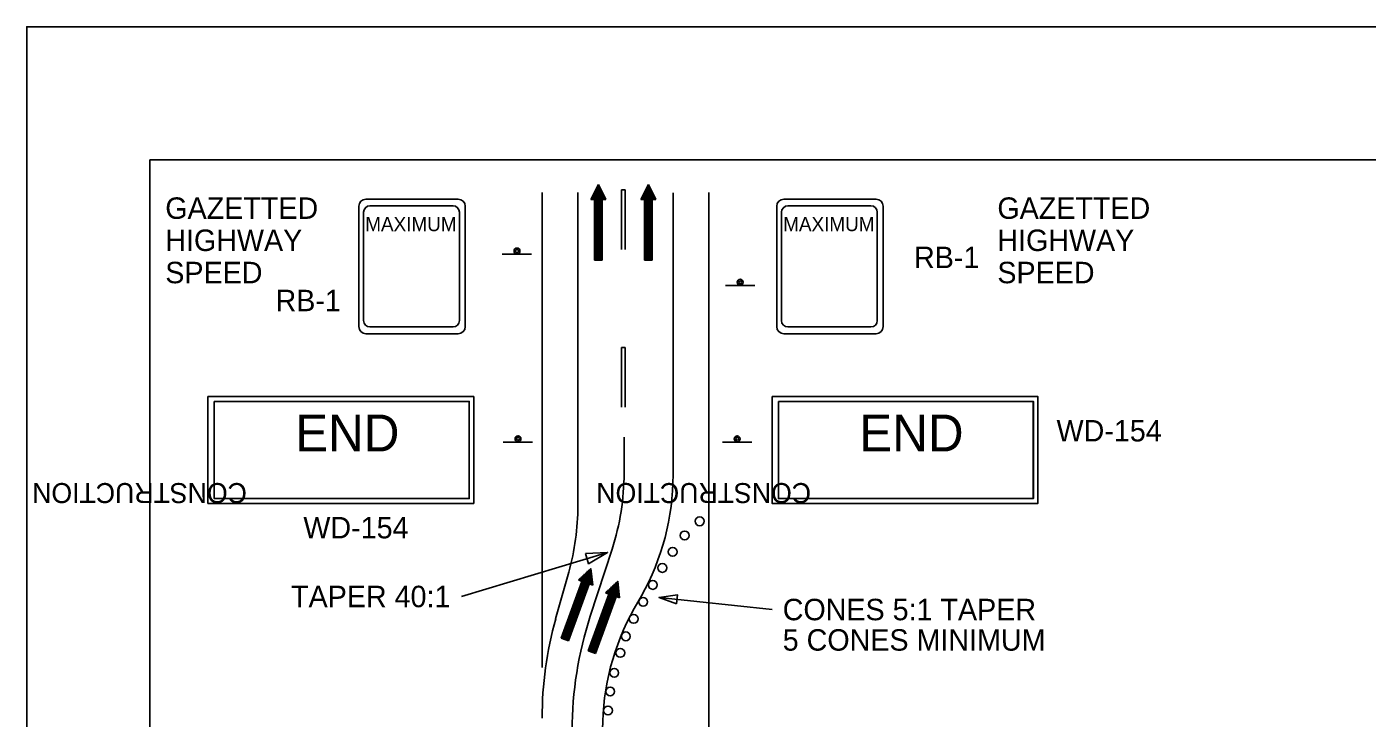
# Model space of a CAD drawing. Extents: x 2171 to 2395, y 134 to 413.
# Drawn here: x 2178.7 to 2287.7, y 356.6 to 412.8 of the extents above; entities that cross this region are included whole.
import ezdxf

# ---------------------------------------------------------------- set-up
doc = ezdxf.new("R2010")
doc.units = 0
for name, color, linetype in [('Level 10', 7, 'Continuous'), ('Level 12', 7, 'Continuous'), ('Level 2', 7, 'Continuous'), ('Level 20', 7, 'Continuous'), ('Level 44', 7, 'Continuous'), ('Level 60', 7, 'Continuous')]:
    doc.layers.add(name, color=color, linetype=linetype)

# ---------------------------------------------------------------- blocks, each defined once
blk = doc.blocks.new('END')
at = {"layer": 'Level 2'}
for points in [[(0, 8.676), (21.598, 8.676), (21.598, 0), (0, 0)], [(0.511, 8.287), (21.224, 8.287), (21.224, 0.397), (0.511, 0.397)]]:
    blk.add_lwpolyline(points, close=True, dxfattribs=at)
at = {"layer": 'Level 44'}
for s, height, rotation, p in [('END', 3, 359.99999, (7.085, 4.219)), ('CONSTRUCTION', 1.62, 179.99999, (3.164, 1.653))]:
    blk.add_text(s, height=height, rotation=rotation, dxfattribs=at).set_placement(p)

msp = doc.modelspace()

# ---------------------------------------------------------------- linework, layer by layer
at = {"layer": 'Level 10'}
for p, q in [((2225.19, 399.95), (2224.58, 398.72)), ((2225.11, 399.8), (2225.11, 393.81)), ((2225.19, 399.95), (2225.19, 393.81)), ((2225.19, 399.95), (2225.8, 398.72)), ((2225.27, 399.8), (2225.27, 393.81)), ((2229.26, 399.95), (2228.64, 398.72)), ((2229.18, 399.8), (2229.18, 393.81)), ((2229.26, 399.95), (2229.26, 393.81)), ((2229.26, 399.95), (2229.87, 398.72)), ((2229.33, 399.8), (2229.33, 393.81)), ((2223.52, 373.85), (2223.52, 399.31)), ((2224.58, 398.72), (2224.88, 398.72)), ((2224.65, 398.88), (2224.65, 398.72)), ((2224.73, 399.03), (2224.73, 398.72)), ((2224.81, 399.18), (2224.81, 398.72)), ((2224.88, 399.34), (2224.88, 393.81)), ((2224.88, 398.72), (2224.88, 393.81)), ((2224.96, 399.49), (2224.96, 393.81)), ((2225.03, 399.64), (2225.03, 393.81)), ((2225.34, 399.64), (2225.34, 393.81)), ((2225.42, 399.49), (2225.42, 393.81)), ((2225.5, 399.34), (2225.5, 393.81)), ((2225.5, 398.72), (2225.5, 393.81)), ((2225.5, 398.72), (2225.8, 398.72)), ((2225.57, 399.18), (2225.57, 398.72)), ((2225.65, 399.03), (2225.65, 398.72)), ((2225.73, 398.88), (2225.73, 398.72)), ((2228.64, 398.72), (2228.95, 398.72)), ((2228.72, 398.88), (2228.72, 398.72)), ((2228.8, 399.03), (2228.8, 398.72)), ((2228.87, 399.18), (2228.87, 398.72)), ((2228.95, 399.34), (2228.95, 393.81)), ((2228.95, 398.72), (2228.95, 393.81)), ((2229.03, 399.49), (2229.03, 393.81)), ((2229.1, 399.64), (2229.1, 393.81)), ((2229.41, 399.64), (2229.41, 393.81)), ((2229.49, 399.49), (2229.49, 393.81)), ((2229.56, 399.34), (2229.56, 393.81)), ((2229.56, 398.72), (2229.56, 393.81)), ((2229.56, 398.72), (2229.87, 398.72)), ((2229.64, 399.18), (2229.64, 398.72)), ((2229.72, 399.03), (2229.72, 398.72)), ((2229.79, 398.88), (2229.79, 398.72)), ((2231.26, 376.36), (2231.26, 399.28)), ((2224.88, 393.81), (2225.5, 393.81)), ((2228.95, 393.81), (2229.56, 393.81)), ((2227.28, 379.44), (2227.28, 376.51)), ((2224.53, 364.88), (2226.3, 370.33)), ((2225.94, 370.07), (2214.07, 366.49)), ((2221.72, 364.68), (2222.78, 368.47)), ((2224.07, 368.3), (2222.18, 363.11)), ((2224.2, 368.42), (2222.26, 363.08)), ((2224.32, 368.54), (2222.33, 363.06)), ((2224.45, 368.65), (2222.4, 363.03)), ((2224.57, 368.77), (2222.47, 363)), ((2224.59, 368.6), (2222.54, 362.98)), ((2224.61, 368.43), (2222.62, 362.95)), ((2224.63, 368.26), (2222.69, 362.93)), ((2224.57, 368.77), (2223.57, 367.83)), ((2223.95, 368.18), (2223.79, 367.75)), ((2224.57, 368.77), (2224.73, 367.41)), ((2223.86, 367.72), (2222.18, 363.11)), ((2224.65, 368.09), (2222.76, 362.9)), ((2224.44, 367.51), (2222.76, 362.9)), ((2223.57, 367.83), (2223.86, 367.72)), ((2223.7, 367.94), (2223.65, 367.8)), ((2223.82, 368.06), (2223.72, 367.78)), ((2226.26, 367.27), (2224.37, 362.08)), ((2224.44, 367.51), (2224.73, 367.41)), ((2226.39, 367.38), (2224.44, 362.05)), ((2224.67, 367.92), (2224.51, 367.49)), ((2226.51, 367.5), (2224.51, 362.03)), ((2224.69, 367.75), (2224.58, 367.46)), ((2226.63, 367.62), (2224.59, 362)), ((2226.76, 367.74), (2224.66, 361.97)), ((2224.71, 367.58), (2224.66, 367.43)), ((2226.78, 367.57), (2224.73, 361.95)), ((2226.8, 367.4), (2224.8, 361.92)), ((2226.82, 367.23), (2224.88, 361.89)), ((2226.84, 367.06), (2224.95, 361.87)), ((2226.76, 367.74), (2225.76, 366.79)), ((2226.14, 367.15), (2225.98, 366.72)), ((2226.76, 367.74), (2226.91, 366.38)), ((2226.05, 366.69), (2224.37, 362.08)), ((2226.63, 366.48), (2224.95, 361.87)), ((2225.76, 366.79), (2226.05, 366.69)), ((2225.89, 366.91), (2225.83, 366.77)), ((2226.01, 367.03), (2225.91, 366.74)), ((2226.63, 366.48), (2226.91, 366.38)), ((2226.86, 366.89), (2226.7, 366.45)), ((2226.88, 366.72), (2226.77, 366.43)), ((2226.9, 366.55), (2226.84, 366.4)), ((2228.11, 365.51), (2228.69, 366.54)), ((2230.13, 366.42), (2239.3, 365.43)), ((2222.18, 363.11), (2222.76, 362.9)), ((2224.37, 362.08), (2224.95, 361.87))]:
    msp.add_line(p, q, dxfattribs=at)
for points in [[(2224.15, 369.98), (2225.94, 370.07), (2224.4, 369.15)], [(2231.54, 365.9), (2230.13, 366.42), (2231.61, 366.63)]]:
    msp.add_lwpolyline(points, close=True, dxfattribs=at)
for centre in [(2233.42, 372.6), (2232.2, 371.45), (2231.23, 370.12), (2230.39, 368.81), (2230.39, 368.81), (2230.39, 368.81), (2229.61, 367.43), (2229.61, 367.43), (2229.61, 367.43), (2228.83, 366.05), (2228.83, 366.05), (2228.83, 366.05), (2228.06, 364.67), (2228.06, 364.67), (2228.06, 364.67), (2227.42, 363.25), (2226.97, 361.91), (2226.48, 360.29), (2226.15, 358.78), (2225.97, 357.23)]:
    msp.add_circle(centre, 0.359, dxfattribs=at)
msp.add_arc((2207.28, 376.51), 20, 341.9995, 0, dxfattribs=at)
at = {"layer": 'Level 12'}
for centre, radius, start, end in [((2211.26, 376.36), 20, 330.6066, 0), ((2203.52, 373.85), 20, 344.3937, 0), ((2253.06, 355.61), 30, 161.9995, 180), ((2245.53, 355.69), 20, 150.6066, 179.9638), ((2250.62, 356.61), 30, 164.3937, 180)]:
    msp.add_arc(centre, radius, start, end, dxfattribs=at)
at = {"layer": 'Level 2'}
for p, q in [((2227.07, 399.51), (2227.07, 394.67)), ((2227.36, 399.51), (2227.07, 399.51)), ((2227.36, 394.67), (2227.36, 399.51)), ((2227.07, 386.7), (2227.07, 381.86)), ((2227.36, 386.7), (2227.07, 386.7)), ((2227.36, 381.86), (2227.36, 386.7))]:
    msp.add_line(p, q, dxfattribs=at)
for points in [[(2193.47, 382.73), (2215.07, 382.73), (2215.07, 374.05), (2193.47, 374.05)], [(2193.98, 382.34), (2214.7, 382.34), (2214.7, 374.44), (2193.98, 374.44)], [(2239.31, 382.73), (2260.91, 382.73), (2260.91, 374.05), (2239.31, 374.05)], [(2239.82, 382.34), (2260.53, 382.34), (2260.53, 374.44), (2239.82, 374.44)]]:
    msp.add_lwpolyline(points, close=True, dxfattribs=at)
at = {"layer": 'Level 20'}
for p, q in [((2220.62, 360.72), (2220.62, 399.31)), ((2234.16, 349.42), (2234.16, 399.31))]:
    msp.add_line(p, q, dxfattribs=at)
at = {"layer": 'Level 44'}
for p, q in [((2206.3, 398.76), (2213.8, 398.76)), ((2240.26, 398.76), (2247.75, 398.76)), ((2205.72, 388.41), (2205.72, 398.18)), ((2206.11, 388.91), (2206.11, 397.7)), ((2206.63, 398.22), (2213.38, 398.22)), ((2213.9, 397.7), (2213.9, 388.91)), ((2214.38, 398.18), (2214.38, 388.41)), ((2239.68, 388.41), (2239.68, 398.18)), ((2240.07, 388.91), (2240.07, 397.7)), ((2240.59, 398.22), (2247.33, 398.22)), ((2247.85, 397.7), (2247.85, 388.91)), ((2248.33, 398.18), (2248.33, 388.41)), ((2217.37, 394.28), (2219.77, 394.28)), ((2235.51, 391.74), (2237.91, 391.74)), ((2206.11, 388.91), (2206.11, 388.91)), ((2240.07, 388.91), (2240.07, 388.91)), ((2205.72, 388.41), (2205.72, 388.41)), ((2213.8, 387.83), (2206.3, 387.83)), ((2213.38, 388.38), (2206.63, 388.38)), ((2239.68, 388.41), (2239.68, 388.41)), ((2247.75, 387.83), (2240.26, 387.83)), ((2247.33, 388.38), (2240.59, 388.38)), ((2217.45, 379.03), (2219.85, 379.03)), ((2235.27, 379.03), (2237.66, 379.03))]:
    msp.add_line(p, q, dxfattribs=at)
for centre, radius in [((2218.58, 394.55), 0.24), ((2218.58, 394.55), 0.12), ((2236.71, 392.01), 0.24), ((2236.71, 392.01), 0.12), ((2218.66, 379.3), 0.24), ((2218.66, 379.3), 0.12), ((2236.47, 379.3), 0.24), ((2236.47, 379.3), 0.12)]:
    msp.add_circle(centre, radius, dxfattribs=at)
for centre, radius, start, end in [((2206.3, 398.18), 0.578, 90, 180), ((2213.8, 398.18), 0.578, 360, 90), ((2240.26, 398.18), 0.578, 90, 180), ((2247.75, 398.18), 0.578, 360, 90), ((2206.63, 397.7), 0.52, 90, 180), ((2213.38, 397.7), 0.52, 360, 90), ((2240.59, 397.7), 0.52, 90, 180), ((2247.33, 397.7), 0.52, 360, 90), ((2206.63, 388.9), 0.52, 180, 270), ((2213.38, 388.9), 0.52, 270, 360), ((2240.59, 388.9), 0.52, 180, 270), ((2247.33, 388.9), 0.52, 270, 360), ((2206.3, 388.41), 0.578, 180, 270), ((2213.8, 388.41), 0.578, 270, 360), ((2240.26, 388.41), 0.578, 180, 270), ((2247.75, 388.41), 0.578, 270, 360)]:
    msp.add_arc(centre, radius, start, end, dxfattribs=at)
at = {"layer": 'Level 60'}
for points in [[(2394.75, 412.76), (2178.75, 412.76), (2178.75, 133.76), (2394.75, 133.76)], [(2375.62, 401.95), (2188.75, 401.95), (2188.75, 144.57), (2375.62, 144.57)]]:
    msp.add_lwpolyline(points, close=True, dxfattribs=at)

# ---------------------------------------------------------------- block references
at = {"layer": 'Level 2'}
for p in [(2193.47, 374.05), (2239.31, 374.05)]:
    msp.add_blockref('END', p, dxfattribs=at)

# ---------------------------------------------------------------- texts
at = {"layer": 'Level 10'}
for s, p in [('GAZETTED', (2190, 397.16)), ('GAZETTED', (2257.61, 397.16)), ('HIGHWAY', (2190, 394.55)), ('HIGHWAY', (2257.61, 394.55)), ('RB-1', (2250.84, 393.16)), ('SPEED', (2190, 391.93)), ('SPEED', (2257.61, 391.93)), ('RB-1', (2198.96, 389.66)), ('WD-154', (2262.42, 379.08)), ('WD-154', (2201.22, 371.21)), ('TAPER 40:1', (2200.22, 365.62)), ('CONES 5:1 TAPER', (2240.17, 364.56)), ('5 CONES MINIMUM', (2240.17, 362.09))]:
    msp.add_text(s, height=1.742, dxfattribs=at).set_placement(p)
at = {"layer": 'Level 44'}
for s, height, rotation, p in [('MAXIMUM', 1.147, 360, (2206.25, 396.16)), ('MAXIMUM', 1.147, 360, (2240.21, 396.16)), ('CONSTRUCTION', 1.6202, 180, (2196.63, 375.7)), ('CONSTRUCTION', 1.6202, 180, (2242.47, 375.7))]:
    msp.add_text(s, height=height, rotation=rotation, dxfattribs=at).set_placement(p)

doc.saveas('drawing.dxf')
